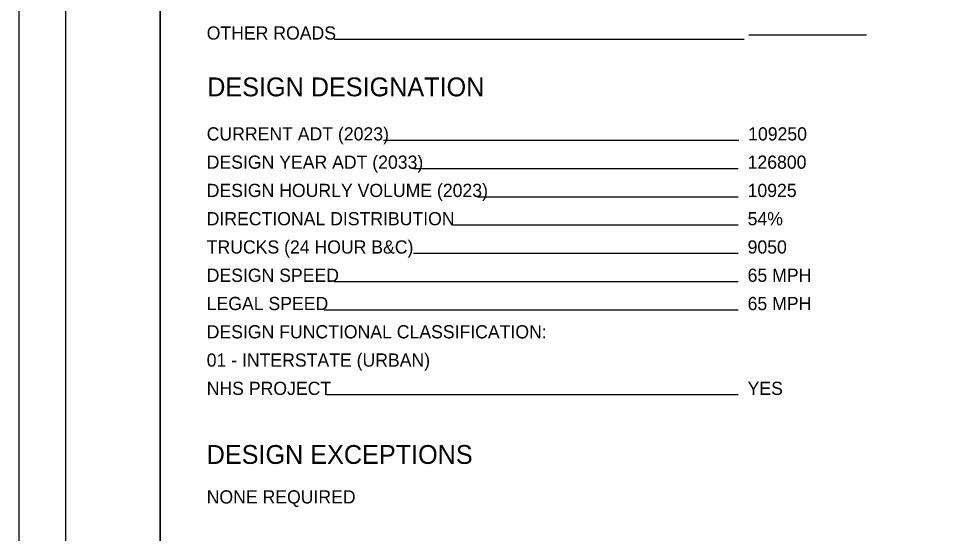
# Model space of a CAD drawing. Extents: x 0 to 34, y 0 to 22.
# Drawn here: x 0 to 9.99, y 5.64 to 11.1 of the extents above; entities that cross this region are included whole.
import ezdxf

# ---------------------------------------------------------------- set-up
doc = ezdxf.new("R2010")
doc.units = 0
for name, color, linetype in [('SH_Border', 7, 'Continuous'), ('SH_Cut_Line', 7, 'Continuous'), ('SH_Data', 7, 'Continuous'), ('SH_Text', 7, 'Continuous')]:
    doc.layers.add(name, color=color, linetype=linetype)

msp = doc.modelspace()

# ---------------------------------------------------------------- linework, layer by layer
at = {"layer": 'SH_Border'}
for points in [[(0.5, 21.5), (1.5, 21.5), (1.5, 0.5), (0.5, 0.5)], [(1.5, 21.5), (33.5, 21.5), (33.5, 0.5), (1.5, 0.5)]]:
    msp.add_lwpolyline(points, close=True, dxfattribs=at)
at = {"layer": 'SH_Cut_Line'}
msp.add_lwpolyline([(0, 0), (34, 0), (34, 22), (0, 22)], close=True, dxfattribs=at)
at = {"layer": 'SH_Data'}
for p, q in [((9, 10.9223), (7.75, 10.9223)), ((7.7, 10.8767), (3.3471, 10.8767)), ((7.6424, 9.8062), (3.871, 9.8062)), ((7.6368, 9.5062), (4.1885, 9.5062)), ((7.6368, 9.2062), (4.8723, 9.2062)), ((7.6368, 8.9062), (4.6037, 8.9062)), ((7.6368, 8.6062), (4.1885, 8.6062)), ((7.6368, 8.3062), (3.346, 8.3062)), ((7.6368, 8.0062), (3.2422, 8.0062)), ((7.6368, 7.1062), (3.2669, 7.1062))]:
    msp.add_line(p, q, dxfattribs=at)

# ---------------------------------------------------------------- texts
msp.add_text('DESIGN DESIGNATION', height=0.2, dxfattribs=at).set_placement((2, 10.2747))
at = {"layer": 'SH_Text'}
for s, height, p in [('OTHER ROADS', 0.14, (1.9944, 10.8767)), ('CURRENT ADT (2023)', 0.14, (1.9944, 9.8062)), ('109250', 0.14, (7.7424, 9.8062)), ('DESIGN YEAR ADT (2033)', 0.14, (1.9944, 9.5062)), ('126800', 0.14, (7.7368, 9.5062)), ('DESIGN HOURLY VOLUME (2023)', 0.14, (1.9944, 9.2062)), ('10925', 0.14, (7.7368, 9.2062)), ('DIRECTIONAL DISTRIBUTION', 0.14, (1.9944, 8.9062)), ('54%', 0.14, (7.7368, 8.9062)), ('TRUCKS (24 HOUR B&C)', 0.14, (1.9944, 8.6062)), ('9050', 0.14, (7.7368, 8.6062)), ('DESIGN SPEED', 0.14, (1.9944, 8.3062)), ('65 MPH', 0.14, (7.7368, 8.3062)), ('LEGAL SPEED', 0.14, (1.9944, 8.0062)), ('65 MPH', 0.14, (7.7368, 8.0062)), ('DESIGN FUNCTIONAL CLASSIFICATION:', 0.14, (1.9944, 7.7062)), ('01 - INTERSTATE (URBAN)', 0.14, (1.9944, 7.4062)), ('NHS PROJECT', 0.14, (1.9944, 7.1062)), ('YES', 0.14, (7.7368, 7.1062)), ('DESIGN EXCEPTIONS', 0.2, (1.9944, 6.3744)), ('NONE REQUIRED', 0.14, (1.9944, 5.9544))]:
    msp.add_text(s, height=height, dxfattribs=at).set_placement(p)

doc.saveas('drawing.dxf')
